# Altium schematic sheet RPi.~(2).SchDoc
size A
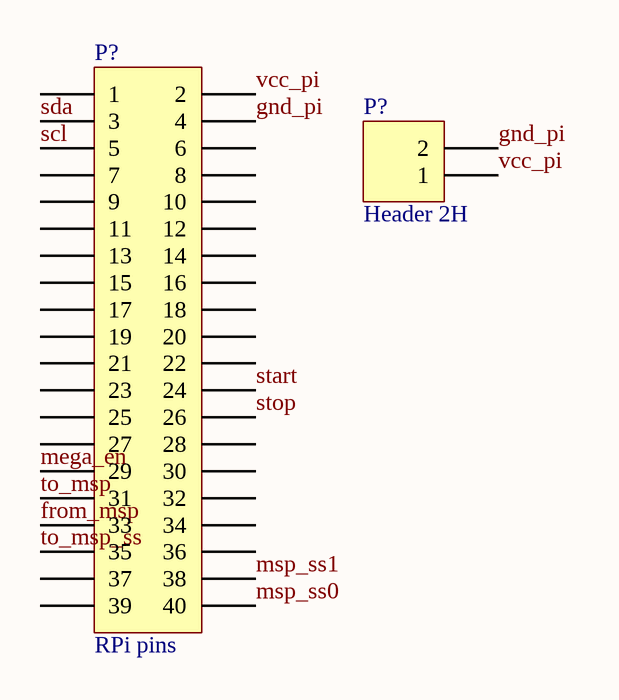
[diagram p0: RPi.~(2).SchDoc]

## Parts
(Parts that share a designator on the sheet are numbered #1, #2 ... from top to bottom, then left to right.)
P?#1  RPi pins  [HDR2X20]
P?#2  Header 2H  [HDR1X2H]

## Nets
from_msp: P?#1.33
gnd_pi: P?#1.4 P?#2.2
mega_en: P?#1.29
msp_ss0: P?#1.40
msp_ss1: P?#1.38
scl: P?#1.5
sda: P?#1.3
start: P?#1.24
stop: P?#1.26
to_msp: P?#1.31
to_msp_ss: P?#1.35
vcc_pi: P?#1.2 P?#2.1

Not connected (* = marked no-connect by the designer): P?#1 1 6 7 8 9 10 11 12 13 14 15 16 17 18 19 20 21 22 23 25 27 28 30 32 34 36 37 39

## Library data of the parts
P?#1 = Header 20X2: Header, 20-Pin, Dual row
P?#2 = Header 2H: Header, 2-Pin, Right Angle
